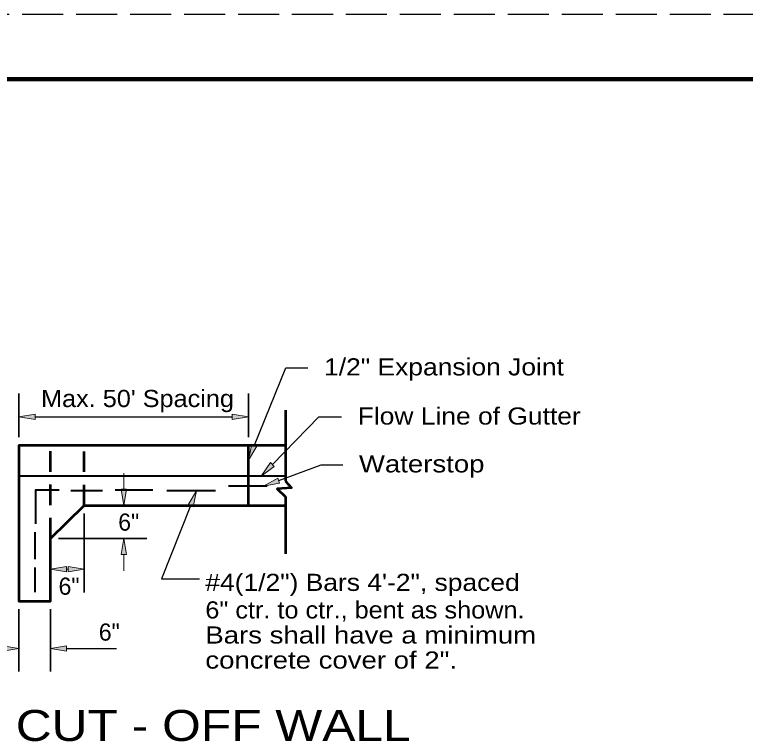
# Model space of a CAD drawing. Extents: x 72.6 to 107.3, y 36.1 to 58.1.
# Drawn here: x 84.21 to 89.87, y 52.45 to 58.08 of the extents above; entities that cross this region are included whole.
import ezdxf

# ---------------------------------------------------------------- set-up
doc = ezdxf.new("R2010")
doc.units = 0
doc.header["$LTSCALE"] = 0.053
doc.linetypes.add('LONG_DASHED', pattern=[7.5, 6, -1.5])
doc.linetypes.add('MEDIUM_DASHED', pattern=[4.5, 3, -1.5])
for name, color, linetype, lineweight in [('1', 7, 'Continuous', 35), ('2', 7, 'MEDIUM_DASHED', 35), ('3', 7, 'Continuous', 13), ('6', 7, 'Continuous', 13)]:
    doc.layers.add(name, color=color, linetype=linetype, lineweight=lineweight)

msp = doc.modelspace()

# ---------------------------------------------------------------- hatches: boundary and pattern name
at = {"layer": '1'}
for points in [[(84.37108, 54.9425), (84.37108, 54.98425), (84.24608, 54.96342), (84.24608, 54.96342)], [(85.8995, 54.9425), (85.8995, 54.98425), (86.0245, 54.96342), (86.0245, 54.96342)], [(84.6155, 53.76033), (84.6155, 53.802), (84.4905, 53.78117), (84.4905, 53.78117)], [(84.62817, 53.76033), (84.62817, 53.802), (84.75317, 53.78117), (84.75317, 53.78117)], [(84.12108, 53.14683), (84.12108, 53.1885), (84.24608, 53.16758), (84.24608, 53.16758)], [(84.6155, 53.14683), (84.6155, 53.1885), (84.4905, 53.16758), (84.4905, 53.16758)]]:
    msp.add_hatch(color=256, dxfattribs=at).paths.add_polyline_path(points)
at = {"layer": '3'}
for points in [[(86.09067, 54.73542), (86.05208, 54.75108), (86.0245, 54.62742), (86.0245, 54.62742)], [(86.22458, 54.57842), (86.19467, 54.60742), (86.12242, 54.50342), (86.12242, 54.50342)], [(86.26642, 54.4485), (86.25183, 54.4875), (86.14208, 54.42425), (86.14208, 54.42425)], [(85.07917, 54.40075), (85.0375, 54.40075), (85.05833, 54.27575), (85.05833, 54.27575)], [(85.55658, 54.281), (85.59533, 54.26567), (85.62183, 54.38958), (85.62183, 54.38958)], [(85.07917, 53.89425), (85.0375, 53.89425), (85.05833, 54.01925), (85.05833, 54.01925)]]:
    msp.add_hatch(color=256, dxfattribs=at).paths.add_polyline_path(points)

# ---------------------------------------------------------------- linework, layer by layer
at = {"layer": '1', "linetype": 'LONG_DASHED', "lineweight": 25}
msp.add_line((107.16175, 58.07983), (72.62475, 58.07983), dxfattribs=at)
at = {"layer": '1', "lineweight": 158}
msp.add_line((107.07842, 57.57983), (74.57842, 57.57983), dxfattribs=at)
at = {"layer": '1'}
for p, q in [((84.24608, 54.80383), (84.24608, 55.14342)), ((86.0245, 54.80383), (86.0245, 55.14342)), ((84.75317, 54.21325), (84.75317, 53.60117)), ((84.24608, 53.47208), (84.24608, 52.98767)), ((84.4905, 53.47208), (84.4905, 52.98767))]:
    msp.add_line(p, q, dxfattribs=at)
at = {"layer": '1', "lineweight": 53}
for p, q in [((86.31208, 55.013), (86.31208, 54.46467)), ((86.0245, 54.27575), (86.0245, 54.74133))]:
    msp.add_line(p, q, dxfattribs=at)
at = {"layer": '1', "lineweight": 25}
for p, q in [((84.37108, 54.96342), (85.8995, 54.96342)), ((84.6155, 53.16767), (84.7405, 53.16767)), ((84.7405, 53.16767), (85.00267, 53.16767))]:
    msp.add_line(p, q, dxfattribs=at)
at = {"layer": '1', "lineweight": 40}
for p, q in [((86.31208, 54.50342), (84.24608, 54.50342)), ((86.17067, 54.42425), (85.869, 54.42425)), ((84.89333, 54.38958), (84.64825, 54.38958)), ((85.2845, 54.39458), (84.99233, 54.39458)), ((85.77, 54.38958), (85.39292, 54.38958)), ((84.37017, 54.068), (84.37017, 53.86017)), ((84.37017, 53.79583), (84.37017, 53.60292))]:
    msp.add_line(p, q, dxfattribs=at)
at = {"layer": '1', "lineweight": 13}
for p, q in [((84.6155, 53.78117), (84.62817, 53.78117)), ((84.4905, 53.72358), (84.4905, 53.60117))]:
    msp.add_line(p, q, dxfattribs=at)
for points in [[(84.37108, 54.9425), (84.37108, 54.98425), (84.24608, 54.96342), (84.24608, 54.96342)], [(85.8995, 54.9425), (85.8995, 54.98425), (86.0245, 54.96342), (86.0245, 54.96342)], [(84.6155, 53.76033), (84.6155, 53.802), (84.4905, 53.78117), (84.4905, 53.78117)], [(84.62817, 53.76033), (84.62817, 53.802), (84.75317, 53.78117), (84.75317, 53.78117)], [(84.12108, 53.14683), (84.12108, 53.1885), (84.24608, 53.16758), (84.24608, 53.16758)], [(84.6155, 53.14683), (84.6155, 53.1885), (84.4905, 53.16758), (84.4905, 53.16758)]]:
    msp.add_lwpolyline(points, close=True, dxfattribs=at)
at = {"layer": '1', "lineweight": 53}
for points in [[(86.31208, 54.74133), (84.24608, 54.74133), (84.24608, 53.53467), (84.4905, 53.53467), (84.4905, 54.01925), (84.75317, 54.27575), (86.31208, 54.27575)], [(86.31208, 54.46467), (86.35725, 54.41325), (86.24742, 54.40392), (86.31208, 54.34225), (86.31208, 53.89975)]]:
    msp.add_lwpolyline(points, dxfattribs=at)
at = {"layer": '1', "lineweight": 40}
msp.add_lwpolyline([(84.55867, 54.39458), (84.37483, 54.39458), (84.37483, 54.13233)], dxfattribs=at)
at = {"layer": '2', "lineweight": 53}
for p, q in [((84.4905, 54.01925), (84.4905, 54.74133)), ((84.75317, 54.27575), (84.75317, 54.74133))]:
    msp.add_line(p, q, dxfattribs=at)
at = {"layer": '3'}
for p, q in [((85.05833, 54.40075), (85.05833, 54.52575)), ((85.05833, 54.01925), (85.05842, 54.01925)), ((85.05833, 53.89425), (85.05833, 53.76925))]:
    msp.add_line(p, q, dxfattribs=at)
at = {"layer": '3', "lineweight": 35}
msp.add_line((84.553, 54.01925), (85.23833, 54.01925), dxfattribs=at)
at = {"layer": '3', "lineweight": 25}
for points in [[(86.07142, 54.74333), (86.31383, 55.34317), (86.48567, 55.34317)], [(86.20967, 54.593), (86.56908, 54.96217), (86.74583, 54.96217)], [(86.25917, 54.46808), (86.58875, 54.59142), (86.75558, 54.59142)], [(85.57592, 54.27333), (85.35183, 53.70558), (85.64642, 53.70558)]]:
    msp.add_lwpolyline(points, dxfattribs=at)
at = {"layer": '3'}
for points in [[(86.09067, 54.73542), (86.05208, 54.75108), (86.0245, 54.62742), (86.0245, 54.62742)], [(86.22458, 54.57842), (86.19467, 54.60742), (86.12242, 54.50342), (86.12242, 54.50342)], [(86.26642, 54.4485), (86.25183, 54.4875), (86.14208, 54.42425), (86.14208, 54.42425)], [(85.07917, 54.40075), (85.0375, 54.40075), (85.05833, 54.27575), (85.05833, 54.27575)], [(85.55658, 54.281), (85.59533, 54.26567), (85.62183, 54.38958), (85.62183, 54.38958)], [(85.07917, 53.89425), (85.0375, 53.89425), (85.05833, 54.01925), (85.05833, 54.01925)]]:
    msp.add_lwpolyline(points, close=True, dxfattribs=at)
at = {"layer": '6'}
for p, q in [((86.0245, 54.96342), (86.02458, 54.96342)), ((84.24608, 54.74133), (84.24617, 54.74133)), ((86.0245, 54.74133), (86.02458, 54.74133)), ((84.24608, 54.50342), (84.24617, 54.50342)), ((84.75317, 54.27575), (84.75325, 54.27575)), ((84.75317, 54.27575), (84.75325, 54.27575)), ((84.4905, 54.01925), (84.49058, 54.01925)), ((84.4905, 53.78608), (84.49058, 53.78608)), ((84.75317, 53.78117), (84.75325, 53.78117)), ((84.24608, 53.53467), (84.24617, 53.53467)), ((84.24608, 53.53458), (84.24617, 53.53458)), ((84.4905, 53.53458), (84.49058, 53.53458)), ((84.4905, 53.16767), (84.49058, 53.16767))]:
    msp.add_line(p, q, dxfattribs=at)

# ---------------------------------------------------------------- texts
at = {"layer": '1'}
msp.add_text('6"', height=0.133, dxfattribs=at).set_placement((84.8655, 53.22767))
at = {"layer": '3'}
for s, height, width, p in [('1/2" Expansion Joint', 0.133, 1.15, (86.61067, 55.28317)), ("Max. 50' Spacing", 0.133, 1.1, (84.41767, 55.03792)), ('Flow Line of Gutter', 0.133, 1.15, (86.87083, 54.90217)), ('Waterstop', 0.133, 1.2, (86.88058, 54.53142)), ('#4(1/2") Bars 4\'-2", spaced', 0.133, 1.15, (85.69058, 53.61292)), ('6" ctr. to ctr., bent as shown.', 0.133, 1.1, (85.69058, 53.39942)), ('Bars shall have a minimum', 0.133, 1.2, (85.69058, 53.20508)), ('concrete cover of 2".', 0.133, 1.2, (85.69058, 53.01083)), ('CUT - OFF WALL', 0.24, 1.2, (84.222, 52.45017))]:
    msp.add_text(s, height=height, dxfattribs=dict(at, width=width)).set_placement(p)
for p in [(85.01608, 54.08), (84.55383, 53.58325)]:
    msp.add_text('6"', height=0.133, dxfattribs=at).set_placement(p)

doc.saveas('drawing.dxf')
